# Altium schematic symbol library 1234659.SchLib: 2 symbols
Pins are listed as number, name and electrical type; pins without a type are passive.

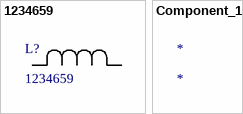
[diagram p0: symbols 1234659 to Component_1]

## 1234659
designator L?
No Description Available; Mfr_Name: RS Pro; Type: DEV
footprint IND_123_4659_RSP
pins: 1, 2

## Component_1
designator *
